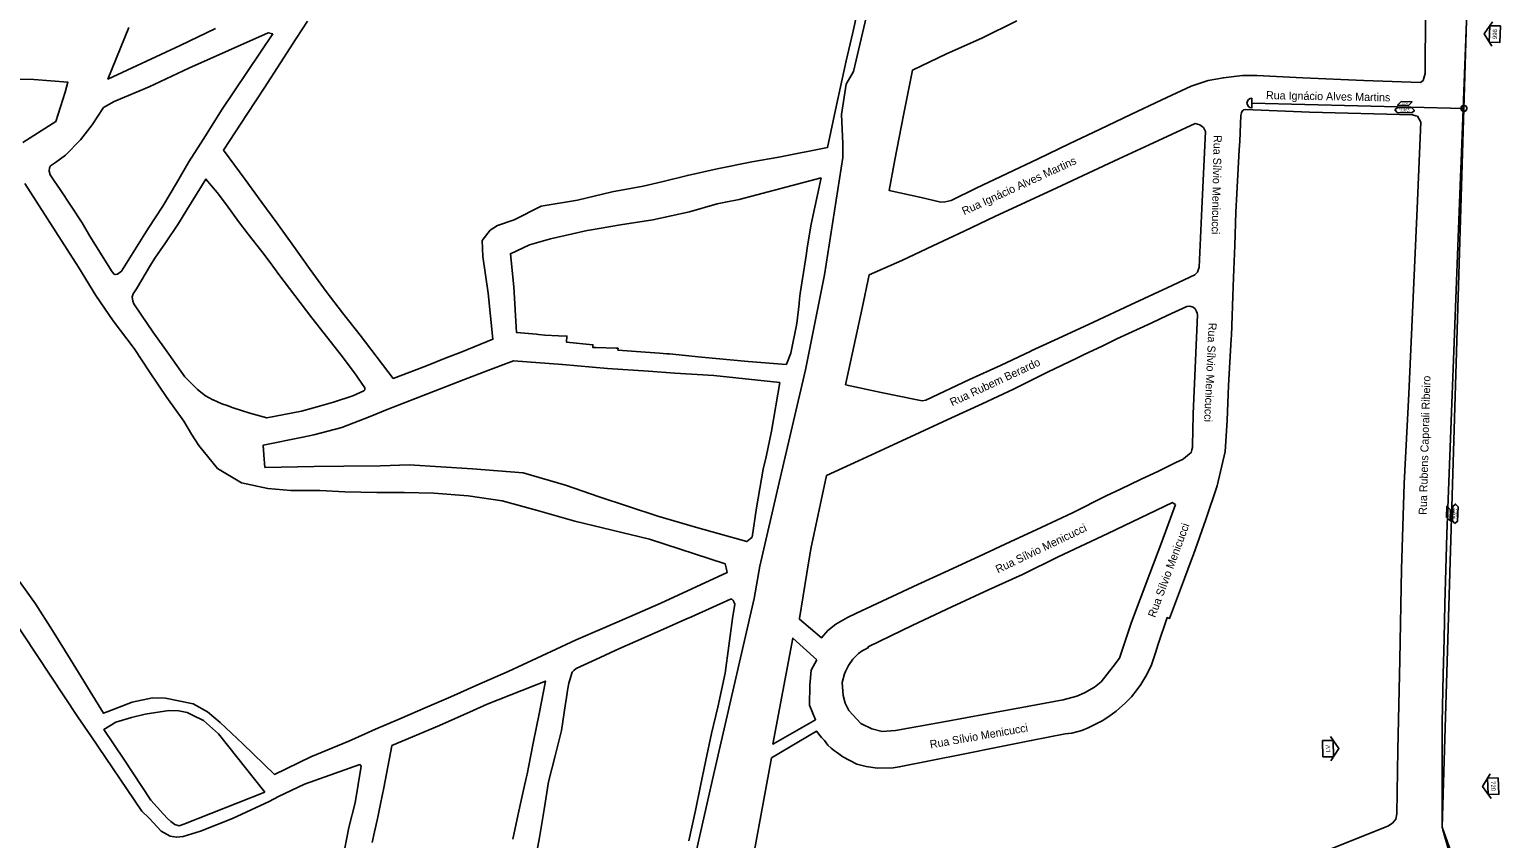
# Model space of a CAD drawing. Extents: x -39999 to 23586, y -25927 to 32541.
# Drawn here: x -2822 to -1535, y -8371 to -7663 of the extents above; entities that cross this region are included whole.
import ezdxf

# ---------------------------------------------------------------- set-up
doc = ezdxf.new("R2010")
doc.units = 0
for name, color, linetype in [('LIMITE_BAIRROS_MUNICIPIOS', 7, 'Continuous'), ('LOGRADOURO_OESTE', 7, 'Continuous'), ('LOGRADOURO_TEXTO', 7, 'Continuous'), ('NUM_REF', 7, 'Continuous'), ('SIMBOLO', 7, 'Continuous'), ('TEXTO', 7, 'Continuous'), ('TUBO_PEAD_GN_63', 7, 'Continuous')]:
    doc.layers.add(name, color=color, linetype=linetype)

# ---------------------------------------------------------------- blocks, each defined once
blk = doc.blocks.new('NUM_REF')
at = {"layer": 'NUM_REF'}
blk.add_lwpolyline([(-4.3125, 0.9375), (0, 3.75), (4.3125, 0.9375)], dxfattribs=at)
blk.add_lwpolyline([(2.875, -1.875), (2.875, 1.875), (-2.875, 1.875), (-2.875, -1.875)], close=True, dxfattribs=at)
blk = doc.blocks.new('INTERLIGACAO')
at = {"layer": 'SIMBOLO'}
blk.add_circle((0, 0), 1.28, dxfattribs=at)
for start, end in [(0, 180), (180, 0)]:
    blk.add_arc((0, 0), 1.28, start, end, dxfattribs=at)

msp = doc.modelspace()

# ---------------------------------------------------------------- linework, layer by layer
at = {"layer": 'LIMITE_BAIRROS_MUNICIPIOS'}
msp.add_lwpolyline([(-1669.8, -6764.8), (-1788.9, -6960), (-1805.4, -6971.8), (-1881.3, -7104.1), (-1958.4, -7231.5), (-2017.8, -7335.4), (-2027.9, -7372.7), (-2046, -7458.1), (-2059.3, -7521.9), (-2100.8, -7699.6), (-2107.3, -7710.7), (-2111.4, -7737.5), (-2110.1, -7762.8), (-2110.3, -7775.1), (-2126.3, -7877.7), (-2142.8, -7960.7), (-2165.8, -8059.3), (-2182.8, -8132.3), (-2187.9, -8160.8), (-2224.3, -8319.1), (-2247.9, -8423.5)], dxfattribs=at)
at = {"layer": 'LOGRADOURO_OESTE'}
for points in [[(-2578.5, -7655.8), (-2588.2, -7670.9), (-2602, -7692.3), (-2616.4, -7714.3), (-2630.8, -7736.4), (-2652, -7768.6), (-2633, -7794.3), (-2618.3, -7814.3), (-2605.2, -7832), (-2590.4, -7852.8), (-2576, -7872.9), (-2562, -7892.1), (-2547.8, -7910.8), (-2532.3, -7930.4), (-2503.4, -7968.2), (-2474.3, -7957.1), (-2457.2, -7950.2), (-2444.1, -7945.2), (-2416.2, -7933.9), (-2420.4, -7893.7), (-2425, -7861.7), (-2425.8, -7847.5), (-2418.6, -7838.5), (-2412.2, -7834.5), (-2397.8, -7829.6), (-2374, -7817.6), (-2342.3, -7812.4), (-2311.9, -7804.9), (-2284.9, -7800.1), (-2268.6, -7796.3), (-2246.2, -7790.6), (-2220, -7784.9), (-2189.9, -7778.8), (-2166.3, -7774.8), (-2123.7, -7766.3), (-2115.9, -7729.3), (-2107.3, -7690.3), (-2101.6, -7665.6), (-2093.3, -7628.3)], [(-1958, -7655.5), (-1988.6, -7670.6), (-2019.6, -7684.4), (-2049.4, -7698.5), (-2057.1, -7737.9), (-2064.6, -7776.9), (-2069.8, -7803.8), (-2041.6, -7810.1), (-2024.6, -7814), (-2020.7, -7813.7), (-2015.5, -7812.6), (-1993.5, -7801.8), (-1966.4, -7788.9), (-1939.4, -7776), (-1912.4, -7763.1), (-1885.3, -7750.2), (-1858.2, -7737.3), (-1831.1, -7724.4), (-1805.7, -7712.5), (-1790.7, -7707.7), (-1777.4, -7705.2), (-1768.1, -7704), (-1760.6, -7703.1), (-1748.1, -7703.2), (-1707.8, -7705.3), (-1654.6, -7707.5), (-1605, -7709.5), (-1602.7, -7707.5), (-1600.9, -7701.5), (-1600.5, -7648.2)], [(-1564.4, -7648.2), (-1567.4, -7724.7), (-1569.2, -7770.7), (-1570.3, -7799.5), (-1571.5, -7829.8), (-1572.7, -7860.3), (-1573.8, -7890.7), (-1575, -7921.3), (-1576.2, -7952), (-1577.4, -7982.2), (-1578.6, -8013.3), (-1579.7, -8043.8), (-1580.8, -8073.7), (-1581.9, -8104.4), (-1582.8, -8135.1), (-1583.8, -8165.5), (-1584.3, -8195.9), (-1585.1, -8226.9), (-1586.2, -8269.6), (-1586.2, -8360.8), (-1585.5, -8363.1), (-1578.7, -8386.5)], [(-2734.6, -7661.2), (-2752.9, -7706.4), (-2689.8, -7677), (-2658.8, -7662.2)], [(-2827.5, -7761.9), (-2798.4, -7743.5), (-2790.5, -7717.7), (-2787.9, -7709.2), (-2817.8, -7706.6), (-2872.8, -7705.6)], [(-1730.6, -8398.6), (-1633.7, -8359.8), (-1629.5, -8357.2), (-1626.6, -8353.8), (-1625.8, -8349.1), (-1624.8, -8293.2), (-1623.2, -8214.5), (-1621.7, -8135.1), (-1619.4, -8060.2), (-1615.1, -7981.7), (-1611.5, -7897.5), (-1608, -7819.7), (-1604.7, -7744), (-1607.7, -7738.9), (-1609.1, -7738.5), (-1612, -7737.6), (-1702, -7735.4), (-1758.4, -7733.1), (-1759.7, -7733.4), (-1759.9, -7733.5), (-1760.9, -7734.3), (-1761.7, -7736), (-1762, -7738.1), (-1763.1, -7760.8), (-1763.5, -7768.2), (-1765.7, -7806.4), (-1766.4, -7822.9), (-1767.4, -7851.8), (-1768.6, -7879.8), (-1769.2, -7896.2), (-1770.3, -7930.7), (-1770.5, -7933.6), (-1772.8, -7974.5), (-1774, -8005), (-1775.7, -8032.1), (-1782.8, -8062.1), (-1792.7, -8091.6), (-1803.5, -8122.1), (-1805.5, -8127.6), (-1811.4, -8143.2), (-1824.5, -8178.1), (-1826.5, -8177.4), (-1834.3, -8200.8), (-1836.8, -8208.3), (-1840.7, -8219.7), (-1845.1, -8228.8), (-1848.6, -8234.4), (-1849.6, -8236), (-1852.7, -8240.2), (-1857.8, -8246.6), (-1863, -8252.1), (-1871.2, -8259.3), (-1877.6, -8264), (-1883.5, -8267.8), (-1886.9, -8269.5), (-1887, -8269.6), (-1895.7, -8273.8), (-1901.2, -8276.1), (-1910, -8278.4), (-1915.8, -8279.1), (-1945.5, -8285), (-1945.5, -8285), (-1974.7, -8290.9), (-2003.6, -8296.6), (-2033.1, -8302.5), (-2060.9, -8308), (-2066.3, -8308.7), (-2079.9, -8309.2), (-2089.8, -8307.6), (-2097.9, -8305.5), (-2110.1, -8299.3), (-2115, -8295.8), (-2117.6, -8293.9), (-2120.3, -8291.7), (-2123.4, -8289), (-2126.4, -8285), (-2128.8, -8282.2), (-2133.2, -8276.8), (-2172.5, -8300.2), (-2194.9, -8420.4)], [(-2837.5, -8135.7), (-2816.4, -8165.4), (-2801.5, -8188.8), (-2785.7, -8214.2), (-2756.7, -8261.1), (-2753.6, -8259.9), (-2731.7, -8251.5), (-2714.1, -8247.7), (-2702.7, -8247.9), (-2678.5, -8253), (-2666, -8260), (-2654.8, -8269.3), (-2635.1, -8287.9), (-2607.4, -8314.6), (-2575.5, -8299.3), (-2542.2, -8285.5), (-2528, -8279), (-2518.9, -8274.9), (-2497.7, -8265.9), (-2473.6, -8255.6), (-2453.1, -8246.8), (-2430.2, -8236.5), (-2403, -8224.6), (-2377.7, -8213), (-2356.5, -8203.1), (-2343.3, -8196.9), (-2320.3, -8187), (-2296.9, -8176.9), (-2269.4, -8164.9), (-2211.5, -8138.1), (-2212.4, -8133.9), (-2213.2, -8130.3), (-2279.3, -8108.8), (-2344.7, -8093.2), (-2377.4, -8083.8), (-2408.2, -8075.3), (-2437.9, -8071), (-2467.8, -8068.7), (-2493.8, -8068.1), (-2517.8, -8068), (-2545.7, -8067.3), (-2567.6, -8066.2), (-2592.9, -8066.2), (-2613.1, -8064.5), (-2636.1, -8059.5), (-2657.2, -8046.9), (-2673.5, -8026.8), (-2680, -8016.9), (-2686.7, -8005.5), (-2701.3, -7984.8), (-2716.5, -7962.5), (-2729.9, -7942.1), (-2748.5, -7917.9), (-2755.9, -7906.9), (-2763.5, -7895.8), (-2778.7, -7870.8), (-2825.6, -7797.8)], [(-2547.9, -8389.6), (-2542.2, -8361), (-2536.8, -8339.5), (-2531.5, -8307.4), (-2532.6, -8306), (-2581, -8323), (-2603.8, -8334), (-2612, -8338.4), (-2644, -8353.2), (-2672.1, -8364.2), (-2687.2, -8368.9), (-2693.1, -8369.6), (-2698.5, -8368.5), (-2706.3, -8364.3), (-2717, -8352.9), (-2723.2, -8346.6), (-2767.9, -8280.9), (-2779.1, -8264.9), (-2851.5, -8155.4)], [(-2244.9, -8372.7), (-2239.1, -8346.2), (-2234.6, -8324.7), (-2230, -8302.1), (-2225, -8278.9), (-2219.4, -8255.7), (-2213.2, -8226.1), (-2206.8, -8178.2), (-2204.6, -8165.8), (-2205.4, -8164.1), (-2206.1, -8162.4), (-2207.4, -8161.3), (-2208.4, -8161.4), (-2242.7, -8176.8), (-2247.4, -8178.9), (-2267, -8187.5), (-2306.1, -8204.7), (-2309.4, -8206.3), (-2322.5, -8212.3), (-2343.4, -8221.9), (-2345.4, -8223.8), (-2346.8, -8225.3), (-2349.8, -8234.8), (-2350.6, -8239.5), (-2351, -8241.3), (-2352.3, -8249.3), (-2352.7, -8252.7), (-2356.2, -8276.1), (-2361.9, -8298.3), (-2367.6, -8321.1), (-2371.5, -8345.2), (-2375.4, -8369.9), (-2379.9, -8393.5)], [(-2398.9, -8371.1), (-2394.1, -8349.4), (-2391.5, -8337.4), (-2389.2, -8327), (-2387.1, -8317.8), (-2386.4, -8314.5), (-2383.3, -8299.2), (-2381, -8287.4), (-2375.6, -8260.2), (-2370.3, -8232.9), (-2421.3, -8253.2), (-2433.5, -8258.8), (-2462.9, -8271.8), (-2504.6, -8289.4), (-2504.7, -8289.5), (-2511.6, -8326.3), (-2514.5, -8340.2), (-2516.6, -8350.4), (-2517.4, -8354.5), (-2519.7, -8364.9), (-2521.8, -8374.2)]]:
    msp.add_lwpolyline(points, dxfattribs=at)
for points in [[(-2608.8, -7666.8), (-2612.7, -7665.8), (-2682.3, -7696.9), (-2716.8, -7713.1), (-2747.4, -7726.1), (-2756.9, -7731.3), (-2766.8, -7746.3), (-2776.9, -7759.4), (-2790.2, -7773), (-2798.9, -7779.3), (-2803.1, -7782.4), (-2804.2, -7784.1), (-2804.3, -7786.9), (-2803.5, -7790), (-2799.9, -7795.4), (-2794.7, -7803), (-2775.6, -7832.2), (-2768.7, -7843.8), (-2749.3, -7875), (-2747.6, -7876.9), (-2746.5, -7877.3), (-2746.4, -7877.3), (-2744.5, -7877), (-2741.1, -7874.4), (-2717.9, -7837.2), (-2704.8, -7817.6), (-2692.9, -7797.4), (-2682.3, -7778.7), (-2669.7, -7759.3), (-2669.1, -7758.4), (-2653.5, -7733.5)], [(-1793.1, -7752.3), (-1794.8, -7748.6), (-1795.7, -7748), (-1798.1, -7746.3), (-1802.2, -7745.3), (-1842.3, -7763.9), (-1868.8, -7776.2), (-1895.8, -7788.8), (-1923, -7801.5), (-1950.2, -7814.1), (-1977.2, -7826.7), (-2004.2, -7839.4), (-2031.5, -7852.3), (-2058.7, -7865.1), (-2087.1, -7877.5), (-2093.4, -7906.8), (-2107.8, -7973.7), (-2107.8, -7973.8), (-2076.6, -7980.4), (-2045.3, -7986.9), (-2040.9, -7987.8), (-2037.7, -7987.2), (-1999.3, -7969.3), (-1972.4, -7956.9), (-1972.3, -7956.9), (-1945.7, -7944.3), (-1945.6, -7944.2), (-1918, -7931.5), (-1891.1, -7918.9), (-1858.7, -7903.9), (-1826.5, -7888.9), (-1802.5, -7877.7), (-1800, -7875.2), (-1798.6, -7870.8), (-1796.2, -7819.7)], [(-2528.2, -7977.3), (-2528.3, -7976.4), (-2537.2, -7963.2), (-2549.1, -7947.9), (-2560.6, -7933), (-2574.6, -7915.1), (-2589.6, -7895.7), (-2603.4, -7877.2), (-2611.2, -7866.8), (-2618.3, -7857.2), (-2630.3, -7841.9), (-2638.8, -7830.9), (-2649.4, -7816.5), (-2657.5, -7805.6), (-2667.2, -7793.8), (-2683.9, -7820.7), (-2691.2, -7832.6), (-2702.7, -7849.5), (-2711.9, -7862.9), (-2715.8, -7869.2), (-2728, -7889.8), (-2731, -7894.1), (-2731.7, -7896.8), (-2731.2, -7900.7), (-2730.4, -7902.9), (-2723.6, -7912.9), (-2713.7, -7927.4), (-2699.8, -7947), (-2685.6, -7966.9), (-2674.7, -7978), (-2667.7, -7983.3), (-2661.2, -7986.8), (-2660.8, -7987), (-2653.4, -7990.5), (-2648.8, -7992), (-2643.3, -7993.8), (-2628.9, -7998.6), (-2625.6, -7999.5), (-2614.1, -8002.7), (-2583.7, -7996.9), (-2567.9, -7992.5), (-2555.8, -7989.1), (-2538.9, -7983.3), (-2529.1, -7979), (-2528.3, -7978.1)], [(-2129.1, -7792.9), (-2200.8, -7811.6), (-2212.9, -7814), (-2220, -7815.5), (-2244.2, -7822.6), (-2276.3, -7829.5), (-2304.6, -7833.9), (-2304.6, -7833.9), (-2331.9, -7838.4), (-2333.8, -7838.7), (-2365.8, -7846.2), (-2384.4, -7851.5), (-2400.9, -7859.2), (-2398, -7888.1), (-2395.6, -7928.1), (-2378.2, -7929.6), (-2376.3, -7929.8), (-2370.9, -7930.3), (-2359, -7930.9), (-2351.5, -7931.2), (-2351.9, -7936.4), (-2328.8, -7938.8), (-2328.9, -7941.1), (-2326.2, -7941.1), (-2308.4, -7941.7), (-2306.8, -7941.8), (-2306.9, -7943.4), (-2286.8, -7944.9), (-2270.5, -7946.1), (-2264.2, -7946.6), (-2261.7, -7946.8), (-2233.7, -7949.5), (-2193.1, -7953.4), (-2159.7, -7956), (-2159.6, -7955.8), (-2155.8, -7946.2), (-2150.5, -7920.3), (-2148.5, -7902.9), (-2148, -7898.6), (-2147.5, -7894), (-2143, -7864.5), (-2142.4, -7860.8), (-2141, -7852.1), (-2137.9, -7833.4)], [(-1799.9, -7912.7), (-1800.4, -7911.1), (-1800.8, -7909.6), (-1802.1, -7907.2), (-1803.7, -7905.8), (-1803.8, -7905.8), (-1806.8, -7905), (-1809.4, -7905.2), (-1826.7, -7913.3), (-1839.9, -7919.5), (-1870.5, -7933.7), (-1875.7, -7936.1), (-1882.9, -7939.6), (-1899.8, -7947.6), (-1905.6, -7950.4), (-1931.2, -7962.7), (-1960.9, -7977.6), (-1988.5, -7990.4), (-2015.1, -8002.7), (-2043, -8015.6), (-2070, -8028.1), (-2096.6, -8040.4), (-2124.4, -8053.2), (-2138.2, -8117.2), (-2141.7, -8138.6), (-2148.1, -8178.2), (-2148.2, -8178.9), (-2128.9, -8195.2), (-2123.3, -8188.7), (-2116.2, -8183.1), (-2106.2, -8177.4), (-2098.3, -8173.5), (-2071.5, -8161), (-2044.7, -8148.6), (-2017.9, -8136.3), (-1990.6, -8123.6), (-1963.8, -8111.2), (-1936.7, -8098.6), (-1909.3, -8085.8), (-1880, -8071), (-1867.4, -8065), (-1849.8, -8056.6), (-1834.2, -8049.2), (-1818.9, -8041.9), (-1813.2, -8039.2), (-1812.4, -8038.5), (-1807, -8034.1), (-1805.7, -8033.1), (-1805, -8030.8), (-1804.4, -8028.6), (-1804.1, -8012), (-1803.8, -8001.5), (-1803.7, -7999.3)], [(-2165.2, -7971.7), (-2223.1, -7965.6), (-2257.2, -7963.6), (-2280.2, -7962), (-2316.1, -7959.5), (-2355.5, -7955.9), (-2398.2, -7952.8), (-2420.6, -7961.2), (-2441.9, -7969.5), (-2499.6, -7991.8), (-2508.7, -7995.4), (-2523.5, -8001.4), (-2548.5, -8011.1), (-2572.9, -8017.6), (-2582.4, -8019.6), (-2617.2, -8026.6), (-2616.5, -8035.1), (-2615.7, -8046), (-2572.7, -8045.4), (-2546.5, -8045), (-2514.6, -8044.8), (-2489.6, -8043.8), (-2434.2, -8047.3), (-2389.9, -8050.9), (-2352.9, -8061.5), (-2323.3, -8071.9), (-2298.6, -8080), (-2272.1, -8088.8), (-2237.1, -8098.9), (-2194.3, -8111), (-2191.2, -8108.5), (-2189.4, -8107), (-2185.7, -8081.4), (-2179.8, -8047.5), (-2177.4, -8036.9), (-2172.5, -8014.3)], [(-1819.4, -8078.6), (-1820.5, -8077.8), (-1821.8, -8076.8), (-1878.5, -8103.8), (-1921.8, -8124.4), (-1953.1, -8139.6), (-1982.8, -8153.2), (-2014.8, -8168.1), (-2049.1, -8184), (-2088.2, -8203.1), (-2087.9, -8203.7), (-2091.1, -8205.2), (-2093.2, -8206.5), (-2096.5, -8208.7), (-2101.5, -8213.7), (-2105.3, -8219.3), (-2107.8, -8224.5), (-2108.8, -8226.6), (-2110.8, -8234.2), (-2110, -8245.6), (-2108.2, -8252.4), (-2105.4, -8258), (-2105.1, -8258.6), (-2094.4, -8270.1), (-2085, -8274.6), (-2075.9, -8277), (-2064.1, -8276.1), (-2022, -8268.6), (-1983.9, -8261.6), (-1949, -8255.3), (-1917.4, -8249.5), (-1905.5, -8246.1), (-1898.9, -8243.2), (-1890.2, -8238.2), (-1884.2, -8233.6), (-1873.9, -8220.3), (-1868.4, -8212.9), (-1857.7, -8181.5), (-1841.6, -8138.9), (-1831.2, -8111.1)], [(-2133.1, -8214.5), (-2153.9, -8195.3), (-2171.4, -8288.1), (-2171, -8287.8), (-2134.1, -8266.8), (-2139.4, -8254), (-2139, -8236.4), (-2137.8, -8223.3)], [(-2615.7, -8330.1), (-2686.7, -8358), (-2690.6, -8359.5), (-2694.4, -8358.4), (-2698, -8355.9), (-2700.8, -8353.1), (-2704.4, -8349.5), (-2715.5, -8337.2), (-2739, -8301.3), (-2756.4, -8275.2), (-2745.9, -8269), (-2732.4, -8264.9), (-2720.3, -8261.9), (-2699.7, -8258.8), (-2690.9, -8259.1), (-2683.7, -8260.5), (-2678.4, -8263), (-2669.4, -8267.4), (-2656.2, -8279.1)]]:
    msp.add_lwpolyline(points, close=True, dxfattribs=at)
at = {"layer": 'SIMBOLO'}
for points in [[(-1627.4, -7733.4), (-1625.1, -7731.2), (-1612.5, -7731.6), (-1610.4, -7733.9), (-1612.6, -7736), (-1625.3, -7735.6), (-1627.4, -7733.4)], [(-1574.9, -8095.2), (-1577, -8092.9), (-1576.6, -8080.3), (-1574.3, -8078.2), (-1572.2, -8080.4), (-1572.6, -8093.1), (-1574.9, -8095.2)]]:
    msp.add_lwpolyline(points, dxfattribs=at)
for points in [[(-1615.5, -7729.5), (-1625.1, -7729.2), (-1622, -7726), (-1612.4, -7726.3)], [(-1578.7, -8083.2), (-1579, -8092.9), (-1582.3, -8089.7), (-1582, -8080.1)]]:
    msp.add_lwpolyline(points, close=True, dxfattribs=at)
at = {"layer": 'TUBO_PEAD_GN_63'}
for p, q in [((-1752.5, -7731.7), (-1752.4, -7723.2)), ((-1752.5, -7727.4), (-1567, -7732))]:
    msp.add_line(p, q, dxfattribs=at)
msp.add_lwpolyline([(-1562.6, -7587.2), (-1586.2, -8360.8), (-1560.1, -8433.6), (-1818.3, -8531), (-1860.7, -8570.9), (-1920.4, -8678.2), (-1978.6, -8785.5), (-2006.9, -8819.4), (-2039, -8843.9), (-2149.6, -8882.5)], dxfattribs=at)
msp.add_arc((-1752.5, -7727.4), 4.25, 89.406, 269.406, dxfattribs=at)

# ---------------------------------------------------------------- block references
at = {"layer": 'NUM_REF'}
for p, xscale, yscale, rotation in [((-1540, -7667), 2.5, 2.5, 88.4325), ((-1685.9, -8292.1), 2.5, 2.4999999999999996, -89.48175869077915), ((-1541.4, -8324.9), 2.5000000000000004, 2.4999999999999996, 92.4719408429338)]:
    msp.add_blockref('NUM_REF', p, dxfattribs=dict(at, xscale=xscale, yscale=yscale, rotation=rotation))
at = {"layer": 'SIMBOLO', "xscale": 1.999999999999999, "yscale": 1.9999999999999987, "rotation": -81.47499999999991}
msp.add_blockref('INTERLIGACAO', (-1567, -7732), dxfattribs=at)

# ---------------------------------------------------------------- texts
for s, rotation, p in [('998', 88.4325, (-1538.2, -7671.4)), ('LV', 90.5182, (-1684, -8295.1)), ('720', 272.4719, (-1543.4, -8320.6))]:
    msp.add_text(s, height=3.75, rotation=rotation).set_placement(p)
at = {"layer": 'LOGRADOURO_TEXTO'}
for s, rotation, p in [('Rua Ignácio Alves Martins', 358.9492, (-1740.2, -7723.9)), ('Rua Sílvio Menicucci', 268.7191, (-1785.8, -7755.3)), ('Rua Ignácio Alves Martins', 24.6285, (-2004.1, -7825.5)), ('Rua Sílvio Menicucci', 267.3781, (-1790.3, -7919.4)), ('Rua Rubem Berardo', 24.9939, (-2014.6, -7992.7)), ('Rua Rubens Caporali Ribeiro', 88.4325, (-1599.6, -8087.6)), ('Rua Sílvio Menicucci', 25.5658, (-1974.6, -8138.8)), ('Rua Sílvio Menicucci', 69.6844, (-1837.1, -8177.9)), ('Rua Sílvio Menicucci', 9.8645, (-2033.5, -8291.9))]:
    msp.add_text(s, height=7, rotation=rotation, dxfattribs=at).set_placement(p)
at = {"layer": 'TEXTO'}
for s, rotation, p in [('DN 63mm', 358.2517, (-1623.6, -7733.2)), ('53,00', 358.2517, (-1621.4, -7728.4)), ('7 Kgf/cm²', 358.2517, (-1623.4, -7735.1)), ('485,85', 88.2527, (-1579.8, -8089.7)), ('DN 63mm', 88.2527, (-1575, -8091.4)), ('7 Kgf/cm²', 88.2527, (-1573.1, -8091.2))]:
    msp.add_text(s, height=1.5, rotation=rotation, dxfattribs=at).set_placement(p)

doc.saveas('drawing.dxf')
